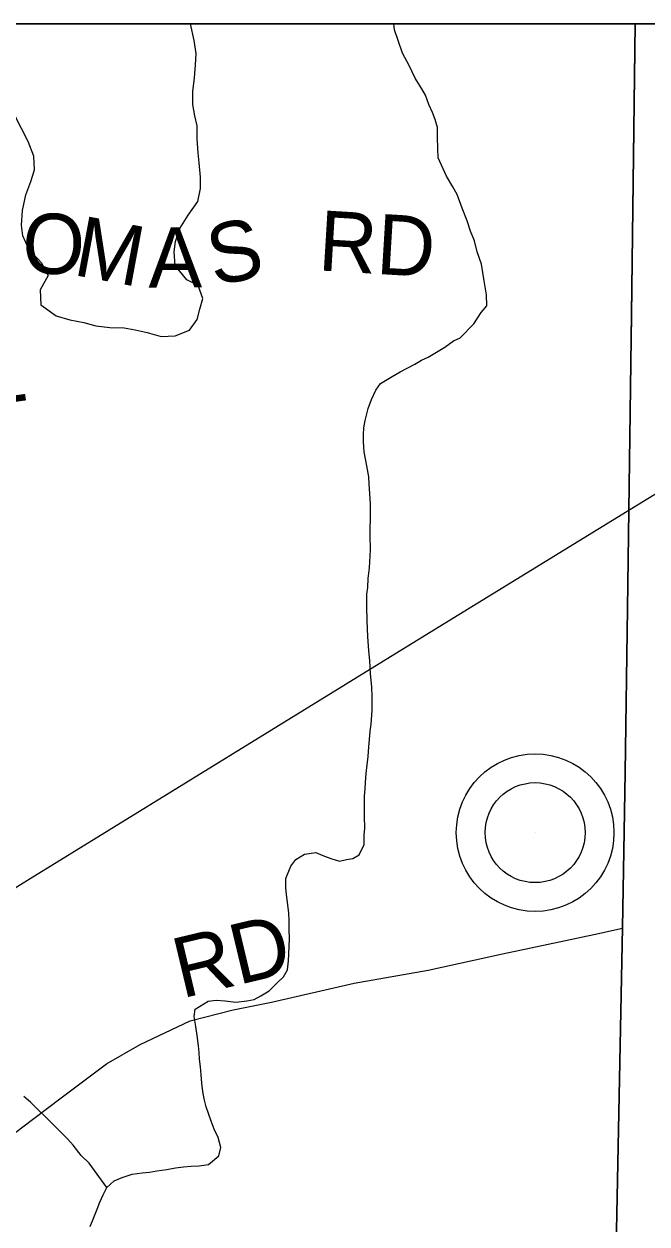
# Model space of a CAD drawing. Extents: x 0 to 34, y 0 to 22.
# Drawn here: x 7.676 to 8.264, y 19.765 to 20.898 of the extents above; entities that cross this region are included whole.
import ezdxf

# ---------------------------------------------------------------- set-up
doc = ezdxf.new("R2010")
doc.units = 0
for name, color, linetype in [('GM_X_Corporation', 7, 'Continuous'), ('GM_X_County_Road', 7, 'Continuous'), ('GM_X_County_Road_Text', 7, 'Continuous'), ('GM_X_Minor_River', 7, 'Continuous'), ('GM_X_Rail_Line', 7, 'Continuous'), ('GM_X_Township_Road', 7, 'Continuous'), ('GM_X_Township_Road_Text', 7, 'Continuous'), ('GM_X_Unincorporated', 7, 'Continuous'), ('GM_X_Unincorporated_Location', 7, 'Continuous'), ('SH_Data', 7, 'Continuous')]:
    doc.layers.add(name, color=color, linetype=linetype)

msp = doc.modelspace()

# ---------------------------------------------------------------- linework, layer by layer
at = {"layer": 'GM_X_Corporation'}
for points in [[(8.2346, 19.7113), (8.2412, 20.0451), (8.2424, 20.1172), (8.2437, 20.1914), (8.2459, 20.3463), (8.2498, 20.6242), (8.2532, 20.898), (2.1, 20.898)], [(8.9, 19.3874), (8.9, 20.898), (8.2532, 20.898), (8.2498, 20.6242), (8.2459, 20.3463), (8.2437, 20.1914), (8.2424, 20.1172), (8.2412, 20.0451), (8.2346, 19.7113)]]:
    msp.add_lwpolyline(points, dxfattribs=at)
at = {"layer": 'GM_X_County_Road'}
msp.add_lwpolyline([(7.2271, 19.6098), (7.2811, 19.6284), (7.3162, 19.6427), (7.3984, 19.6777), (7.4886, 19.7223), (7.5157, 19.7379), (7.5777, 19.7818), (7.6742, 19.8562), (7.7116, 19.8844), (7.7542, 19.9166), (7.7862, 19.9347), (7.8333, 19.9572), (7.8737, 19.9675), (7.91, 19.9746), (7.988, 19.9925), (8.0578, 20.005), (8.1281, 20.0204), (8.2142, 20.0385), (8.2414, 20.0445)], dxfattribs=at)
at = {"layer": 'GM_X_Minor_River'}
for points in [[(7.6926, 20.673), (7.6811, 20.6854), (7.6753, 20.698), (7.674, 20.708), (7.675, 20.722), (7.678, 20.7368), (7.6828, 20.7493), (7.6864, 20.7602), (7.6856, 20.7732), (7.6805, 20.787), (7.674, 20.7993), (7.667, 20.8128), (7.6604, 20.8254), (7.6516, 20.8389), (7.6393, 20.8495), (7.6293, 20.8584), (7.6174, 20.8708), (7.6073, 20.879), (7.5961, 20.888), (7.5815, 20.8974), (7.5804, 20.898)], [(7.6926, 20.673), (7.6993, 20.6606), (7.6918, 20.6471), (7.6923, 20.633), (7.7068, 20.6225), (7.7197, 20.6188), (7.7329, 20.6162), (7.7442, 20.613), (7.7574, 20.6116), (7.7711, 20.6113), (7.7813, 20.6092), (7.7926, 20.6067), (7.8058, 20.603), (7.8191, 20.6038), (7.8325, 20.6089), (7.8399, 20.619), (7.8424, 20.6288), (7.8453, 20.639), (7.8407, 20.6513), (7.8301, 20.6564), (7.819, 20.67), (7.8182, 20.6829), (7.8195, 20.6928), (7.8236, 20.7049), (7.8315, 20.7176), (7.8405, 20.7304), (7.843, 20.7428), (7.8429, 20.7535), (7.8417, 20.7668), (7.8407, 20.7763), (7.8399, 20.7893), (7.8398, 20.8018), (7.8377, 20.8114), (7.8357, 20.8221), (7.8359, 20.8342), (7.8373, 20.8471), (7.8384, 20.8593), (7.839, 20.8703), (7.837, 20.8825), (7.8336, 20.898)], [(8.0002, 20.3347), (7.9999, 20.3483), (8, 20.3597), (8.0008, 20.3662), (8.0012, 20.3745), (8.0024, 20.3848), (8.0033, 20.4018), (8.003, 20.4155), (8.0036, 20.4372), (8.0036, 20.4451), (8.0023, 20.4641), (8.0019, 20.4706), (8.0001, 20.4808), (7.9976, 20.4942), (7.9969, 20.5037), (7.9969, 20.5105), (7.9973, 20.5169), (7.9985, 20.5238), (8.0013, 20.5351), (8.0043, 20.5435), (8.0086, 20.5525), (8.0128, 20.5586), (8.0238, 20.5653), (8.0314, 20.5698), (8.0454, 20.5769), (8.0515, 20.5806), (8.0579, 20.5836), (8.0735, 20.5929), (8.0819, 20.5989), (8.088, 20.6019), (8.1009, 20.6151), (8.1078, 20.6257), (8.1131, 20.6321), (8.1128, 20.6423), (8.1107, 20.6556), (8.1081, 20.6712), (8.104, 20.683), (8.1015, 20.6933), (8.0978, 20.7025), (8.0948, 20.7123), (8.09, 20.7242), (8.0851, 20.7371), (8.081, 20.7444), (8.0751, 20.7543), (8.0706, 20.7646), (8.0672, 20.7718), (8.0669, 20.7806), (8.0666, 20.7912), (8.0667, 20.8003), (8.0645, 20.8079), (8.0619, 20.8144), (8.0585, 20.822), (8.0552, 20.8308), (8.0518, 20.8369), (8.0455, 20.8468), (8.0399, 20.8587), (8.0335, 20.8705), (8.0295, 20.8823), (8.0261, 20.8926), (8.0254, 20.898)], [(7.7389, 19.7628), (7.7424, 19.7715), (7.7454, 19.7794), (7.7481, 19.7859), (7.7512, 19.7927), (7.7547, 19.7999), (7.7615, 19.8062), (7.7691, 19.8092), (7.7786, 19.8122), (7.7881, 19.8136), (7.7949, 19.8143), (7.8017, 19.8154), (7.8111, 19.8168), (7.8195, 19.8182), (7.827, 19.8193), (7.8342, 19.82), (7.8418, 19.8203), (7.8505, 19.8214), (7.8604, 19.8296), (7.8623, 19.8376), (7.8598, 19.8471), (7.856, 19.8547), (7.8531, 19.8623), (7.8505, 19.8696), (7.8483, 19.876), (7.8464, 19.8836), (7.8453, 19.8905), (7.8443, 19.8981), (7.8436, 19.906), (7.8429, 19.9136), (7.8422, 19.9209), (7.8418, 19.9273), (7.8411, 19.9334), (7.84, 19.9433), (7.8386, 19.9516), (7.8371, 19.9611), (7.838, 19.968), (7.8501, 19.9758), (7.8577, 19.9765), (7.8664, 19.976), (7.8762, 19.9748), (7.8868, 19.9759), (7.8936, 19.9773), (7.9001, 19.9807), (7.9077, 19.9855), (7.9149, 19.9927), (7.9214, 19.9987), (7.9252, 20.0051), (7.926, 20.0138), (7.9269, 20.0343), (7.9266, 20.0438), (7.9267, 20.0518), (7.9263, 20.0586), (7.9242, 20.0765), (7.9235, 20.0826), (7.9236, 20.0913), (7.9282, 20.103), (7.9331, 20.1094), (7.9411, 20.1143), (7.9517, 20.1161), (7.9585, 20.113), (7.966, 20.1102), (7.9743, 20.1079), (7.9808, 20.1094), (7.9868, 20.1104), (7.9929, 20.1138), (7.9975, 20.1236), (7.9976, 20.1324), (7.998, 20.1388), (7.9977, 20.1502), (7.9979, 20.1692), (7.9983, 20.176), (7.9987, 20.1821), (7.9995, 20.1904), (8.0003, 20.1988), (8.0012, 20.2067), (8.002, 20.2158), (8.0024, 20.2227), (8.0032, 20.2306), (8.004, 20.2371), (8.0049, 20.25), (8.005, 20.2629), (8.0047, 20.2724), (8.0036, 20.2845), (8.0029, 20.2971), (8.0019, 20.3062), (8.0008, 20.3199), (8.0002, 20.3347)], [(7.7547, 19.7999), (7.7378, 19.8228), (7.7303, 19.8301), (7.7228, 19.8396), (7.7176, 19.8457), (7.7067, 19.8565), (7.6973, 19.8657), (7.6894, 19.8733), (7.6827, 19.8802), (7.6763, 19.8856)]]:
    msp.add_lwpolyline(points, dxfattribs=at)
at = {"layer": 'GM_X_Rail_Line'}
for points in [[(8.2498, 20.4407), (8.8203, 20.7899), (8.9, 20.8387)], [(6.9536, 19.6458), (7.2249, 19.8148), (7.5897, 20.0343), (7.6823, 20.0915), (8.0551, 20.3211), (8.2498, 20.4407)]]:
    msp.add_lwpolyline(points, dxfattribs=at)
at = {"layer": 'GM_X_Township_Road'}
for p, q in [((8.2501, 20.6236), (8.2534, 20.898)), ((8.2475, 20.4416), (8.2501, 20.6236)), ((8.2461, 20.3457), (8.2474, 20.4339)), ((8.2474, 20.4339), (8.2475, 20.4416)), ((8.2439, 20.1908), (8.2461, 20.3457)), ((8.2427, 20.1166), (8.2439, 20.1908)), ((8.2414, 20.0445), (8.2427, 20.1166))]:
    msp.add_line(p, q, dxfattribs=at)
at = {"layer": 'GM_X_Unincorporated'}
for radius in [0.0744, 0.0472]:
    msp.add_circle((8.1588, 20.1347), radius, dxfattribs=at)
at = {"layer": 'GM_X_Unincorporated_Location'}
msp.add_line((8.1588, 20.1347), (8.1588, 20.1347), dxfattribs=at)
at = {"layer": 'SH_Data'}
msp.add_line((2.1, 20.898), (8.9, 20.898), dxfattribs=at)

# ---------------------------------------------------------------- texts
at = {"layer": 'GM_X_County_Road_Text'}
msp.add_text('RD', height=0.05682, rotation=13.4401, dxfattribs=at).set_placement((7.8253, 19.9781))
at = {"layer": 'GM_X_Township_Road_Text'}
for s, height, rotation, p in [('O', 0.0568, 357.3617, (7.6736, 20.6635)), ('RD', 0.05682, 356.5467, (7.9532, 20.6655)), ('M', 0.0568, 349.4191, (7.7215, 20.6614)), ('A', 0.0568, 0.3576, (7.7939, 20.6491)), ('S', 0.0568, 11.4433, (7.8558, 20.6506)), ('1', 0.0568, 8.1297, (7.6402, 20.5373))]:
    msp.add_text(s, height=height, rotation=rotation, dxfattribs=at).set_placement(p)

doc.saveas('drawing.dxf')
